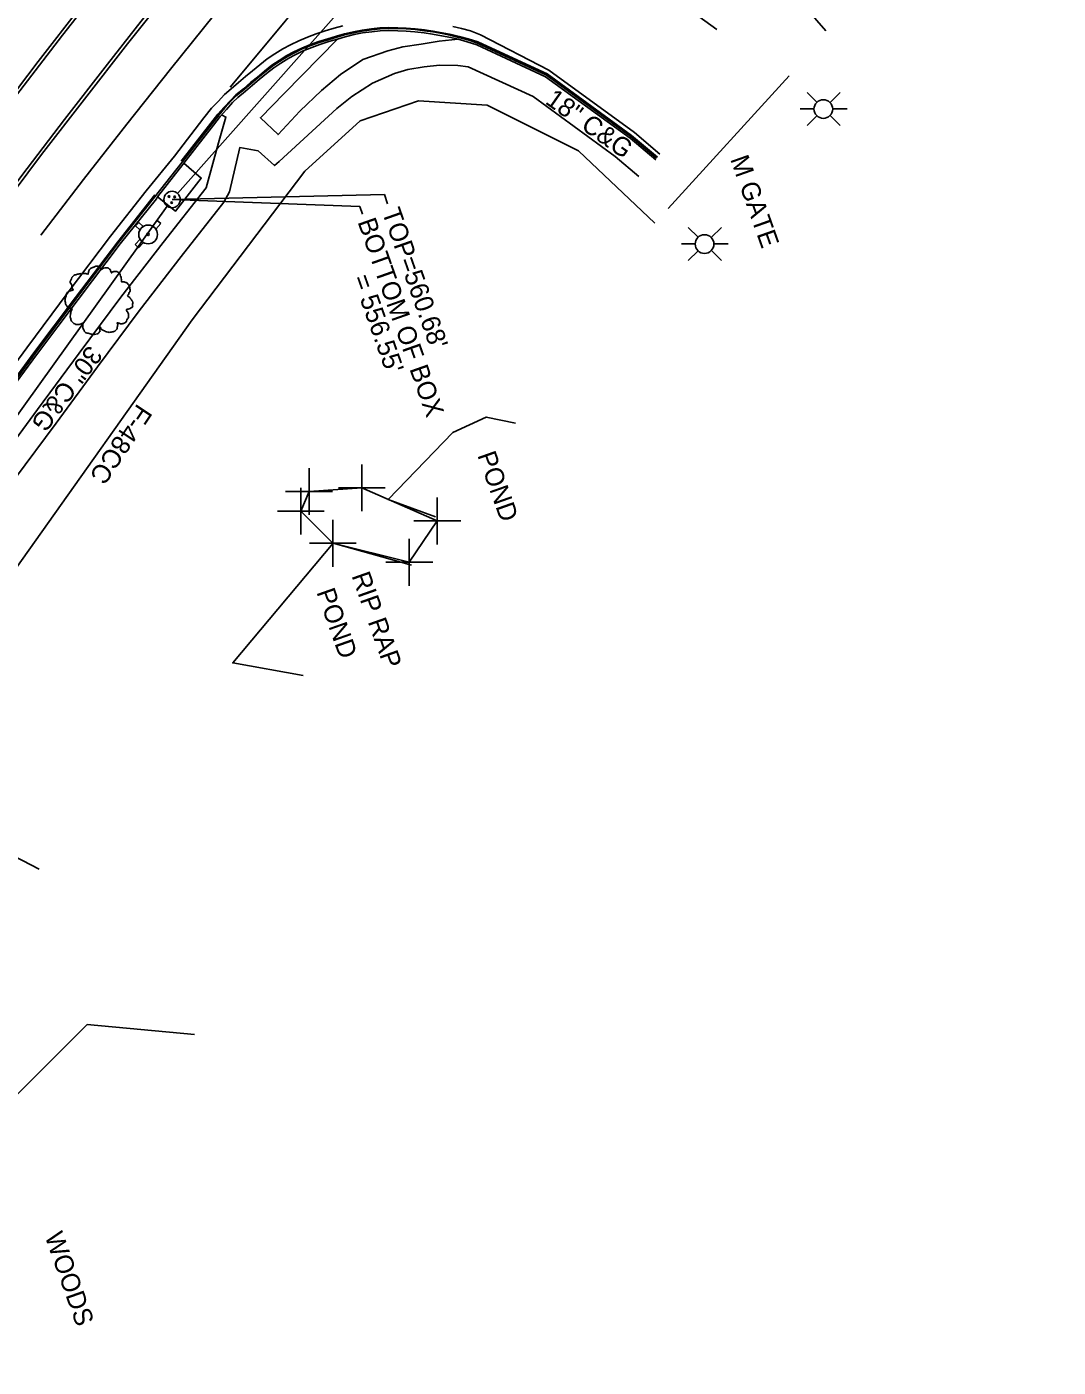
# Model space of a CAD drawing. Extents: x 2004847 to 2009016, y 1134161 to 1140101.
# Drawn here: x 2008054.1 to 2008274.4, y 1139048 to 1139334.3 of the extents above; entities that cross this region are included whole.
import ezdxf

# ---------------------------------------------------------------- set-up
doc = ezdxf.new("R2010")
doc.units = 0
for name, color, linetype in [('RD_EX_Conc', 7, 'Continuous'), ('RD_EX_Curb', 7, 'Continuous'), ('RD_EX_DR_Inlet', 7, 'Continuous'), ('RD_EX_DR_Inlet_txCode', 7, 'Continuous'), ('RD_EX_DR_Pipe', 7, 'Continuous'), ('RD_EX_DV_Prop_txCode', 7, 'Continuous'), ('RD_EX_Fence_ChLk', 7, 'Continuous'), ('RD_EX_H2O', 7, 'Continuous'), ('RD_EX_Misc', 7, 'Continuous'), ('RD_EX_Pavement_Markings', 7, 'Continuous'), ('RD_EX_Road', 7, 'Continuous'), ('RD_EX_UT', 7, 'Continuous'), ('RD_EX_VEG', 7, 'Continuous'), ('RD_Sketch3', 7, 'Continuous')]:
    doc.layers.add(name, color=color, linetype=linetype)

msp = doc.modelspace()

# ---------------------------------------------------------------- linework, layer by layer
at = {"layer": 'RD_EX_Conc'}
for points in [[(2008120.43, 1139331.67), (2008109.08, 1139320.08), (2008104.01, 1139314.89), (2008107.78, 1139311.3), (2008112.41, 1139316.33), (2008117.01, 1139320.68), (2008121.07, 1139324.15), (2008125.89, 1139327.3), (2008131.18, 1139329.18), (2008134.38, 1139330.04), (2008138.36, 1139330.61), (2008142.14, 1139331.23), (2008146.25, 1139331.65)], [(2008148.33, 1139325.77), (2008146.15, 1139326.03), (2008142.25, 1139326.13), (2008138.95, 1139325.79), (2008135.45, 1139325.21), (2008132.65, 1139324.37), (2008127.96, 1139322.31), (2008123.53, 1139319.46), (2008120.35, 1139316.87), (2008108.01, 1139305.56), (2008107.03, 1139304.66), (2008103.54, 1139307.8), (2008099.59, 1139308.51), (2008097.39, 1139299.08), (2008096.21, 1139296.88), (2008087.09, 1139285.23), (2008078.1, 1139273.64), (2008069.2, 1139261.65), (2008060.35, 1139249.66), (2008051.45, 1139237.66), (2008042.51, 1139225.66), (2008033.55, 1139213.58), (2008024.84, 1139201.61), (2008016.3, 1139189.47)], [(2008148.33, 1139325.77), (2008162.28, 1139319.41), (2008179.74, 1139306.61), (2008184.84, 1139302.31)], [(2008095.85, 1139315.46), (2008096.64, 1139315.03), (2008095.02, 1139309.56), (2008092.42, 1139299.95), (2008083.26, 1139288.25), (2008074.18, 1139276.59), (2008065.27, 1139264.59), (2008056.41, 1139252.57), (2008047.5, 1139240.56), (2008038.55, 1139228.56), (2008029.57, 1139216.52), (2008020.83, 1139204.5), (2008012.26, 1139192.32)]]:
    msp.add_lwpolyline(points, dxfattribs=at)
at = {"layer": 'RD_EX_Curb'}
for points in [[(2008094.92, 1139315.64), (2008096.25, 1139317.14), (2008097.61, 1139318.6), (2008098.77, 1139319.76), (2008100.36, 1139321.08), (2008101.87, 1139322.39), (2008103.35, 1139323.58), (2008104.89, 1139324.86), (2008106.45, 1139326.1), (2008107.99, 1139327.1), (2008109.67, 1139328.17), (2008111.16, 1139328.95), (2008112.86, 1139329.78), (2008114.72, 1139330.53), (2008116.47, 1139331.2), (2008118.39, 1139331.77), (2008120.22, 1139332.34), (2008121.94, 1139332.83), (2008123.89, 1139333.24), (2008125.73, 1139333.57), (2008127.71, 1139333.86), (2008129.52, 1139334.07), (2008131.34, 1139334.18), (2008133.34, 1139334.13), (2008135.16, 1139334.05), (2008137.05, 1139333.9), (2008139.03, 1139333.67), (2008140.85, 1139333.41), (2008142.81, 1139333.05), (2008144.77, 1139332.65), (2008146.43, 1139332.24), (2008148.36, 1139331.72), (2008150.45, 1139331.12)], [(2008095.12, 1139315.44), (2008096.41, 1139316.98), (2008097.74, 1139318.47), (2008098.88, 1139319.62), (2008100.5, 1139320.91), (2008102, 1139322.23), (2008103.48, 1139323.41), (2008105.02, 1139324.68), (2008106.58, 1139325.93), (2008108.1, 1139326.92), (2008109.79, 1139327.99), (2008111.25, 1139328.76), (2008112.94, 1139329.58), (2008114.8, 1139330.33), (2008116.56, 1139330.93), (2008118.46, 1139331.56), (2008120.29, 1139332.1), (2008121.99, 1139332.58), (2008123.94, 1139333.03), (2008125.76, 1139333.39), (2008127.74, 1139333.68), (2008129.54, 1139333.86), (2008131.34, 1139333.96), (2008133.34, 1139333.94), (2008135.15, 1139333.86), (2008137.02, 1139333.71), (2008139.01, 1139333.48), (2008140.81, 1139333.21), (2008142.78, 1139332.85), (2008144.73, 1139332.45), (2008146.37, 1139332.05), (2008148.3, 1139331.53), (2008150.38, 1139330.8)], [(2008095.42, 1139315.14), (2008096.08, 1139315.89), (2008096.74, 1139316.65), (2008098.07, 1139318.14), (2008099.18, 1139319.22), (2008100.79, 1139320.55), (2008102.3, 1139321.86), (2008103.76, 1139323.04), (2008105.3, 1139324.31), (2008106.86, 1139325.55), (2008108.36, 1139326.52), (2008110.04, 1139327.6), (2008111.44, 1139328.33), (2008113.12, 1139329.15), (2008114.97, 1139329.89), (2008116.69, 1139330.55), (2008118.6, 1139331.15), (2008120.43, 1139331.67), (2008122.08, 1139332.14), (2008124.01, 1139332.69), (2008125.82, 1139333), (2008127.8, 1139333.27), (2008129.57, 1139333.45), (2008131.34, 1139333.54), (2008133.34, 1139333.49), (2008135.12, 1139333.41), (2008136.97, 1139333.27), (2008138.96, 1139333.04), (2008140.73, 1139332.77), (2008142.7, 1139332.41), (2008144.66, 1139332.04), (2008146.25, 1139331.65), (2008148.18, 1139331.13), (2008150.23, 1139330.49)], [(2008150.38, 1139330.8), (2008165.1, 1139323.96), (2008183.13, 1139310.89), (2008188.62, 1139306.23)], [(2008150.45, 1139331.12), (2008165.22, 1139324.26), (2008183.26, 1139311.13), (2008188.83, 1139306.48)], [(2008150.23, 1139330.49), (2008164.91, 1139323.64), (2008182.93, 1139310.55), (2008188.44, 1139305.92)], [(2008095.12, 1139315.44), (2008093.66, 1139313.55), (2008087.32, 1139305.4), (2008081.37, 1139297.93), (2008073.72, 1139288.24), (2008064.72, 1139276.34), (2008055.85, 1139264.47), (2008047.11, 1139252.64), (2008038.15, 1139240.62), (2008029.34, 1139228.66), (2008020.66, 1139216.92), (2008011.95, 1139204.72), (2008006.14, 1139196.56)], [(2008095.42, 1139315.14), (2008093.96, 1139313.31), (2008087.63, 1139305.16), (2008087.4, 1139304.92), (2008082.01, 1139297.96), (2008081.79, 1139297.6), (2008074.08, 1139287.97), (2008065.11, 1139276.05), (2008056.19, 1139264.21), (2008047.45, 1139252.39), (2008038.51, 1139240.36), (2008029.71, 1139228.4), (2008021.03, 1139216.67), (2008012.28, 1139204.5), (2008006.49, 1139196.32)], [(2008094.92, 1139315.64), (2008093.4, 1139313.74), (2008087.06, 1139305.6)], [(2008081.45, 1139298.4), (2008073.53, 1139288.38), (2008064.48, 1139276.52), (2008055.6, 1139264.65), (2008046.86, 1139252.81), (2008037.95, 1139240.77), (2008029.13, 1139228.81), (2008020.45, 1139217.06), (2008011.69, 1139204.9), (2008005.92, 1139196.72)]]:
    msp.add_lwpolyline(points, dxfattribs=at)
at = {"layer": 'RD_EX_DR_Inlet'}
msp.add_lwpolyline([(2008082.01, 1139297.96), (2008085.88, 1139294.96), (2008091.35, 1139302.01), (2008087.63, 1139305.16)], dxfattribs=at)
for centre, radius in [((2008085.14, 1139297.42), 1.75), ((2008084.47, 1139298.05), 0.175), ((2008085.05, 1139296.76), 0.175), ((2008085.7, 1139297.98), 0.175)]:
    msp.add_circle(centre, radius, dxfattribs=at)
at = {"layer": 'RD_EX_DR_Inlet_txCode'}
for points in [[(2008085.14, 1139297.42), (2008130.47, 1139298.49), (2008131.16, 1139296.52)], [(2008085.14, 1139297.42), (2008125.22, 1139295.92), (2008125.79, 1139294.3)]]:
    msp.add_lwpolyline(points, dxfattribs=at)
at = {"layer": 'RD_EX_DR_Pipe'}
for p, q in [((2008274.37, 1139510.63), (2008086.3, 1139298.73)), ((2008084.12, 1139296), (2007979.21, 1139149.88))]:
    msp.add_line(p, q, dxfattribs=at)
at = {"layer": 'RD_EX_DV_Prop_txCode'}
for p, q in [((2008114.39, 1139230.04), (2008114.39, 1139240.04)), ((2008125.67, 1139230.83), (2008125.67, 1139240.83)), ((2008109.39, 1139235.04), (2008119.39, 1139235.04)), ((2008112.62, 1139225.83), (2008112.62, 1139235.83)), ((2008120.67, 1139235.83), (2008130.67, 1139235.83)), ((2008141.78, 1139223.75), (2008141.78, 1139233.75)), ((2008107.62, 1139230.83), (2008117.62, 1139230.83)), ((2008119.45, 1139218.99), (2008119.45, 1139228.99)), ((2008136.78, 1139228.75), (2008146.78, 1139228.75)), ((2008135.8, 1139214.93), (2008135.8, 1139224.93)), ((2008114.45, 1139223.99), (2008124.45, 1139223.99)), ((2008130.8, 1139219.93), (2008140.8, 1139219.93))]:
    msp.add_line(p, q, dxfattribs=at)
at = {"layer": 'RD_EX_Fence_ChLk'}
for p, q in [((2008216.93, 1139323.83), (2008191.09, 1139295.48)), ((2008188.26, 1139292.38), (2008171.94, 1139307.85)), ((2008056.75, 1139154.38), (2008027.45, 1139169.56))]:
    msp.add_line(p, q, dxfattribs=at)
msp.add_lwpolyline([(2008027.45, 1139169.56), (2008051.77, 1139218.58), (2008089.44, 1139271.69), (2008113.52, 1139303.51), (2008125.32, 1139314.26), (2008137.73, 1139318.51), (2008152.41, 1139317.6), (2008171.94, 1139307.85)], dxfattribs=at)
at = {"layer": 'RD_EX_H2O'}
for points in [[(2008158.49, 1139249.67), (2008152.21, 1139250.94), (2008145.08, 1139247.62), (2008131.27, 1139233.32), (2008141.42, 1139229.67)], [(2008136.26, 1139219.31), (2008119.57, 1139223.99), (2008098.08, 1139198.43), (2008113.15, 1139195.72)]]:
    msp.add_lwpolyline(points, dxfattribs=at)
at = {"layer": 'RD_EX_Misc'}
msp.add_lwpolyline([(2008114.39, 1139235.04), (2008125.67, 1139235.83), (2008141.78, 1139228.75), (2008135.8, 1139219.93), (2008119.45, 1139223.99), (2008112.62, 1139230.83), (2008114.39, 1139235.04)], dxfattribs=at)
at = {"layer": 'RD_EX_Pavement_Markings'}
for points in [[(2007973.46, 1139210.66), (2007982.28, 1139223.44), (2007990.81, 1139235.78), (2007999.38, 1139248.08), (2008008.08, 1139260.31), (2008016.79, 1139272.51), (2008025.63, 1139284.63), (2008034.56, 1139296.69), (2008043.5, 1139308.73), (2008052.62, 1139320.64), (2008061.76, 1139332.53), (2008070.97, 1139344.37), (2008080.36, 1139356.07), (2008089.77, 1139367.76), (2008099.32, 1139379.32), (2008108.89, 1139390.87), (2008118.51, 1139402.38), (2008128.29, 1139413.75), (2008138.1, 1139425.1), (2008148.01, 1139436.36), (2008157.99, 1139447.56), (2008167.91, 1139458.51)], [(2007983.12, 1139205.05), (2007991.61, 1139217.42), (2008000.13, 1139229.76), (2008008.7, 1139242.07), (2008017.44, 1139254.26), (2008026.22, 1139266.43), (2008035.08, 1139278.53), (2008044.05, 1139290.55), (2008053.03, 1139302.57), (2008062.15, 1139314.48), (2008071.34, 1139326.33), (2008080.59, 1139338.14), (2008089.96, 1139349.85), (2008099.35, 1139361.55), (2008108.82, 1139373.18), (2008118.38, 1139384.74), (2008127.97, 1139396.27), (2008137.71, 1139407.68), (2008147.48, 1139419.06), (2008157.38, 1139430.33), (2008167.41, 1139441.48), (2008175.36, 1139450.34)], [(2008152.69, 1139442.67), (2008142.4, 1139431.03), (2008132.52, 1139419.74), (2008122.73, 1139408.38), (2008113.04, 1139396.93), (2008103.43, 1139385.41), (2008093.91, 1139373.81), (2008084.44, 1139362.18), (2008075.07, 1139350.47), (2008065.73, 1139338.73), (2008056.54, 1139326.88), (2008047.42, 1139314.97), (2008038.37, 1139303.01), (2008029.45, 1139290.95), (2008020.58, 1139278.85), (2008011.82, 1139266.67), (2008003.11, 1139254.46), (2007994.46, 1139242.21), (2007985.9, 1139229.89), (2007977.39, 1139217.54)], [(2008057.09, 1139289.8), (2008066.24, 1139301.69), (2008075.49, 1139313.5), (2008084.77, 1139325.28), (2008094.2, 1139336.94), (2008103.68, 1139348.57), (2008113.21, 1139360.16), (2008122.84, 1139371.65), (2008132.49, 1139383.14), (2008142.3, 1139394.49), (2008152.18, 1139405.78), (2008164.57, 1139419.83), (2008186.84, 1139444.6)], [(2008162.04, 1139434.55), (2008152.06, 1139423.19), (2008142.17, 1139411.91), (2008132.47, 1139400.47), (2008122.81, 1139388.99), (2008113.25, 1139377.44), (2008103.73, 1139365.85), (2008094.34, 1139354.15), (2008084.95, 1139342.45), (2008075.65, 1139330.68), (2008066.44, 1139318.84), (2008057.22, 1139307.01), (2008048.22, 1139295.01), (2008039.24, 1139282.99), (2008030.35, 1139270.91), (2008021.59, 1139258.74), (2008012.83, 1139246.56), (2008004.13, 1139234.34), (2007995.64, 1139221.98), (2007986.72, 1139209.15)], [(2008097.52, 1139321.44), (2008108.31, 1139334.31), (2008110.65, 1139337.14), (2008113.05, 1139340.05), (2008120.99, 1139349.67), (2008122.59, 1139351.58), (2008132.62, 1139363.51), (2008138.4, 1139370.47), (2008144.35, 1139377.64), (2008146.42, 1139380.1), (2008151.04, 1139385.6), (2008154.07, 1139389.21), (2008161.38, 1139397.91), (2008170.02, 1139408.12), (2008175.93, 1139415.1)]]:
    msp.add_lwpolyline(points, dxfattribs=at)
at = {"layer": 'RD_EX_Road'}
for points in [[(2008201.46, 1139333.71), (2008186.36, 1139344.71), (2008177.34, 1139352.71), (2008171.19, 1139363.53)], [(2008093.58, 1139316.96), (2008094.98, 1139318.39), (2008096.34, 1139319.86), (2008097.73, 1139321.1), (2008099.29, 1139322.39), (2008100.8, 1139323.71), (2008102.33, 1139324.94), (2008103.88, 1139326.21), (2008105.44, 1139327.46), (2008107.08, 1139328.52), (2008108.76, 1139329.6), (2008110.45, 1139330.49), (2008112.23, 1139331.35), (2008114.08, 1139332.09), (2008115.92, 1139332.8), (2008117.81, 1139333.45), (2008119.72, 1139334), (2008121.59, 1139334.52)], [(2008145.09, 1139334.39), (2008146.95, 1139333.94), (2008148.88, 1139333.42), (2008151, 1139332.63)], [(2008151, 1139332.63), (2008165.62, 1139325.05), (2008183.86, 1139311.73), (2008189.31, 1139307.13)], [(2008093.58, 1139316.96), (2008091.93, 1139314.89), (2008085.64, 1139306.71), (2008079.63, 1139299.28), (2008071.97, 1139289.56), (2008062.98, 1139277.64), (2008054.1, 1139265.76), (2008045.34, 1139253.9), (2008036.48, 1139241.83), (2008027.69, 1139229.83), (2008018.99, 1139218.06), (2008010.23, 1139205.9), (2008004.46, 1139197.72)]]:
    msp.add_lwpolyline(points, dxfattribs=at)
at = {"layer": 'RD_EX_UT'}
for p, q in [((2008220.75, 1139320.3), (2008222.84, 1139318.21)), ((2008225.65, 1139318.14), (2008227.82, 1139320.3)), ((2008222.21, 1139316.77), (2008219.28, 1139316.77)), ((2008229.28, 1139316.77), (2008226.21, 1139316.77)), ((2008220.75, 1139313.23), (2008222.82, 1139315.31)), ((2008225.67, 1139315.38), (2008227.82, 1139313.23)), ((2008078.01, 1139292.54), (2008077.34, 1139291.8)), ((2008077.34, 1139291.8), (2008078.28, 1139290.94)), ((2008078.97, 1139291.66), (2008078.01, 1139292.54)), ((2008081.98, 1139292.94), (2008080.89, 1139291.76)), ((2008081.65, 1139291.11), (2008082.72, 1139292.27)), ((2008082.72, 1139292.27), (2008081.98, 1139292.94)), ((2008195.38, 1139291.46), (2008197.47, 1139289.37)), ((2008200.28, 1139289.3), (2008202.45, 1139291.46)), ((2008078.3, 1139288.93), (2008077.25, 1139287.79)), ((2008077.25, 1139287.79), (2008077.99, 1139287.11)), ((2008077.99, 1139287.11), (2008079.01, 1139288.23)), ((2008196.84, 1139287.93), (2008193.91, 1139287.93)), ((2008203.91, 1139287.93), (2008200.84, 1139287.93)), ((2008195.38, 1139284.39), (2008197.46, 1139286.47)), ((2008200.3, 1139286.54), (2008202.45, 1139284.39))]:
    msp.add_line(p, q, dxfattribs=at)
for centre, radius in [((2008224.21, 1139316.75), 2), ((2008080.02, 1139289.96), 2), ((2008080.02, 1139289.96), 0.25), ((2008198.84, 1139287.91), 2)]:
    msp.add_circle(centre, radius, dxfattribs=at)
for start, end in [(121.7044, 150.6716), (35.1439, 64.1202), (210.7976, 239.7739)]:
    msp.add_arc((2008080.02, 1139289.96), 2, start, end, dxfattribs=at)
at = {"layer": 'RD_EX_VEG'}
for points in [[(2008179.79, 1139404.61), (2008184.62, 1139396.74), (2008186.5, 1139384.8), (2008188.46, 1139377.12), (2008194, 1139368.83), (2008224.73, 1139333.47)], [(2008089.91, 1139119.04), (2008067.01, 1139121.21), (2008041.57, 1139095.83), (2008015.2, 1139074.58), (2008004.96, 1139047.99)]]:
    msp.add_lwpolyline(points, dxfattribs=at)
for points in [[(2008069.33, 1139283.18), (2008069.03, 1139283.2), (2008068.7, 1139283.1), (2008068.45, 1139283), (2008068.23, 1139282.93), (2008068, 1139282.83), (2008067.7, 1139282.66), (2008067.48, 1139282.46), (2008067.35, 1139282.21), (2008067.3, 1139281.98), (2008067.25, 1139281.71), (2008067.25, 1139281.53), (2008067.13, 1139281.51), (2008066.98, 1139281.53), (2008066.73, 1139281.61), (2008066.48, 1139281.61), (2008066.23, 1139281.61), (2008065.88, 1139281.58), (2008065.53, 1139281.58), (2008065.26, 1139281.53), (2008064.93, 1139281.48), (2008064.56, 1139281.36), (2008064.21, 1139281.23), (2008063.91, 1139280.98), (2008063.66, 1139280.51), (2008063.53, 1139280.16), (2008063.38, 1139279.91), (2008063.53, 1139279.46), (2008063.71, 1139279.11), (2008063.73, 1139278.91), (2008063.81, 1139278.48), (2008063.91, 1139278.26), (2008064.03, 1139278.06), (2008063.96, 1139278.03), (2008063.58, 1139277.98), (2008063.28, 1139277.88), (2008062.86, 1139277.66), (2008062.63, 1139277.43), (2008062.53, 1139277.11), (2008062.51, 1139276.76), (2008062.41, 1139276.56), (2008062.33, 1139276.28), (2008062.31, 1139276.21), (2008062.26, 1139275.88), (2008062.36, 1139275.43), (2008062.38, 1139275.08), (2008062.51, 1139274.86), (2008062.66, 1139274.68), (2008062.83, 1139274.43), (2008063.23, 1139274.21), (2008063.56, 1139274.11), (2008063.76, 1139274.08), (2008063.58, 1139273.58), (2008063.53, 1139273.23), (2008063.41, 1139272.83), (2008063.41, 1139272.76), (2008063.36, 1139272.28), (2008063.51, 1139271.96), (2008063.58, 1139271.58), (2008063.76, 1139271.36), (2008064.03, 1139271.06), (2008064.36, 1139270.84), (2008064.86, 1139270.71), (2008065.26, 1139270.74), (2008065.83, 1139270.91), (2008066.08, 1139270.99), (2008066.06, 1139270.81), (2008066.08, 1139270.44), (2008066.08, 1139270.01), (2008066.23, 1139269.69), (2008066.33, 1139269.41), (2008066.48, 1139269.16), (2008066.81, 1139268.94), (2008067.2, 1139268.86), (2008067.63, 1139268.71), (2008068.08, 1139268.64), (2008068.58, 1139268.61), (2008069.18, 1139268.76), (2008069.45, 1139268.89), (2008069.55, 1139269.06), (2008069.75, 1139269.44), (2008069.7, 1139269.66), (2008069.73, 1139270.26), (2008069.83, 1139270.09), (2008070, 1139269.74), (2008070.5, 1139269.44), (2008070.9, 1139269.26), (2008071.38, 1139269.11), (2008071.68, 1139269.04), (2008072.15, 1139269.11), (2008072.53, 1139269.19), (2008072.9, 1139269.31), (2008073.2, 1139269.59), (2008073.38, 1139269.86), (2008073.43, 1139270.14), (2008073.5, 1139270.51), (2008073.55, 1139270.69)], [(2008073.55, 1139270.69), (2008073.48, 1139270.86), (2008073.43, 1139271.11), (2008073.5, 1139271.09), (2008073.68, 1139271.04), (2008073.95, 1139270.91), (2008074.18, 1139270.84), (2008074.5, 1139270.86), (2008074.78, 1139270.96), (2008075.23, 1139271.24), (2008075.5, 1139271.71), (2008075.78, 1139272.11), (2008075.85, 1139272.43), (2008075.8, 1139272.66), (2008075.78, 1139273.16), (2008075.58, 1139273.41), (2008075.53, 1139273.53), (2008075.43, 1139273.93), (2008075.5, 1139273.98), (2008075.78, 1139274.03), (2008076.15, 1139274.16), (2008076.43, 1139274.28), (2008076.65, 1139274.46), (2008076.73, 1139274.68), (2008076.7, 1139275.08), (2008076.75, 1139275.48), (2008076.68, 1139275.63), (2008076.58, 1139275.78), (2008076.5, 1139275.98), (2008076.35, 1139276.13), (2008076.25, 1139276.28), (2008076.15, 1139276.38), (2008076.03, 1139276.53), (2008075.85, 1139276.66), (2008075.7, 1139276.71), (2008075.65, 1139276.86), (2008075.8, 1139277.06), (2008075.85, 1139277.16), (2008075.88, 1139277.38), (2008076.1, 1139277.73), (2008076.15, 1139278.13), (2008076.1, 1139278.56), (2008076.05, 1139278.83), (2008075.9, 1139279.11), (2008075.7, 1139279.36), (2008075.58, 1139279.53), (2008075.4, 1139279.66), (2008075.08, 1139279.78), (2008074.83, 1139279.83), (2008074.48, 1139279.83), (2008074.28, 1139279.88), (2008074.3, 1139279.93), (2008074.3, 1139280.08), (2008074.3, 1139280.36), (2008074.23, 1139280.81), (2008074.08, 1139281.31), (2008074.08, 1139281.33), (2008073.98, 1139281.58), (2008073.75, 1139281.78), (2008073.58, 1139281.88), (2008073.38, 1139282.01), (2008073.13, 1139282.03), (2008072.83, 1139282.03), (2008072.55, 1139281.98), (2008072.35, 1139281.88), (2008072.18, 1139281.76), (2008072.1, 1139281.91), (2008072, 1139282.21), (2008071.95, 1139282.36), (2008071.8, 1139282.53), (2008071.58, 1139282.73), (2008071.13, 1139282.85), (2008070.5, 1139282.78), (2008070.2, 1139282.58), (2008070.05, 1139282.41), (2008070, 1139282.53), (2008069.8, 1139282.73), (2008069.7, 1139282.9), (2008069.53, 1139283.03), (2008069.38, 1139283.13), (2008069.28, 1139283.18)]]:
    msp.add_spline(points, degree=3, dxfattribs=at)

# ---------------------------------------------------------------- texts
at = {"layer": 'RD_EX_DR_Inlet_txCode'}
for s, p in [('BOTTOM OF BOX', (2008124.7, 1139292.66)), ("TOP=560.68'", (2008129.9, 1139294.81)), ("= 556.55'", (2008123.64, 1139280.63))]:
    msp.add_text(s, height=4, rotation=289.4494, dxfattribs=at).set_placement(p)
at = {"layer": 'RD_Sketch3'}
for s, rotation, p in [('18" C&G', 324.7149, (2008164.61, 1139318.06)), ('M GATE', 289.4494, (2008204.28, 1139306.06)), ('30" C&G', 233.2785, (2008067.34, 1139266.52)), ('F-48CC', 236.3005, (2008077.78, 1139254.01)), ('POND', 289.4494, (2008150.29, 1139242.82)), ('RIP RAP', 289.4494, (2008123.42, 1139217.07)), ('POND', 289.4494, (2008115.92, 1139213.57)), ('WOODS', 289.4494, (2008057.87, 1139076.04))]:
    msp.add_text(s, height=4, rotation=rotation, dxfattribs=at).set_placement(p)

doc.saveas('drawing.dxf')
